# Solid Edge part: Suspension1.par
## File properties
Author: KULL
Template: Iso Metric Part.par
Last saved by: KULL
Revision: 5
Application: Solid Edge
Accuracy: 0,990
Face Style: Model Default
Fill Style: Normal
Coef. of Thermal Exp: 0.0
Thermal Conductivity: 0.0
Specific Heat: 0.0
Modulus of Elasticity: 0.0
Poisson's Ratio: 0.0
Yield Stress: 0.0
Ultimate Stress: 0.0
Elongation: 0.0
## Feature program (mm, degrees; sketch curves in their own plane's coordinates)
sketch for "unnamed RevolvedProtrusion 1" plane through (0, 0, 0) normal (1, 0, 0) x-axis (0, 1, 0)
  line (73.196, 15.5693) -> (77.2742, 17.8066)
  line (73.196, 15.5693) -> (74.5585, 13.0856)
  arc centre (63.4726, 33.2936) radius 23.0491 from (74.5585, 13.0856) to (80.8832, 18.1896) ccw
  line (80.2099, 19.417) -> (80.8832, 18.1896)
  line (79.3784, 18.9609) -> (80.2099, 19.417)
revolve "unnamed RevolvedProtrusion 1" add finite 360 deg
sketch for "ExtrudedProtrusion_1" plane through (1.5, 0, 0) normal (1, 0, 0) x-axis (0, 1, 0)
  arc centre (76.2697, 9.9663) radius 3 from (79.1872, 10.6649) to (74.1129, 7.8811) cw
  line (74.1129, 7.8811) -> (70.4123, 11.7087)
  line (70.4123, 11.7087) -> (77.9476, 15.8425)
  line (79.1872, 10.6649) -> (77.9476, 15.8425)
extrude "ExtrudedProtrusion_1" add finite 2.4 along +normal
mirror "unnamed Mirror 1" of "ExtrudedProtrusion_1" about plane through (0, 0, 0) normal (1, 0, 0)
extrude "unnamed Protrusion 1" add finite 2.4
sketch for "ExtrudedProtrusion_3" plane through (0, 0, 0) normal (1, 0, 0) x-axis (0, 1, 0)
  circle centre (76.2697, 9.9663) radius 1.5
extrude "ExtrudedProtrusion_3" add finite 10 symmetric
fillet "Round_1" radius 0.4
fillet "Round_2" radius 0.8
fillet "Round_3" radius 0.8
fillet "Round_4" radius 0.8
fillet "Round_5" radius 0.2
body pattern "unnamed BodyPattern 1"
pattern "unnamed Pattern 1"
sketch used by "ExtrudedProtrusion_4" plane through (0, 73.196, 15.5693) normal (0, -0.480968, 0.876738) x-axis (0, 0.876738, 0.480968)
extrude "ExtrudedProtrusion_4" add finite 19.3627 along +normal
sketch used by "ExtrudedProtrusion_5" plane through (0, 59.9207, 39.7682) normal (0, 0.480968, -0.876738) x-axis (1, 0, 0)
extrude "ExtrudedProtrusion_5" add finite 18.621 along +normal
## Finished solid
Body 1: solid body, 83 faces, 152 edges, 72 vertices.
  Faces by surface: torus 26, plane 25, cylinder 22, blend 8, sphere 2
  Edges by curve: circle 96, line 32, intersection 24
Bounding box of the edges (mm; curved faces can reach further): 16.000 x 28.107 x 41.405, from (-8, 52.5049, 6.9663) to (8, 80.6118, 48.3711).
Cylindrical faces by radius (mm): R0.8 x8, R1.5 x6, R3 x5, R4 x1, R8 x2
Toroidal faces (ring radius, tube radius in mm): R1.1 r0.4 x4, R2.2 r0.8 x4, R5.8516 r1.2 x2, R7.2 r0.8 x2, R7.8 r0.2 x2, R21.2565 r0.8 x8, R23.3814 r0.8 x4
Spherical faces by radius (mm): R23.0491 x2
Planar faces by outward normal: +x 6, -x 6, oblique 13
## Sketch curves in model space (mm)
circle centre (0, 59.9207, 39.7682) radius 4
circle centre (0, 73.196, 15.5693) radius 3
line (0, 73.196, 15.5693) -> (0, 59.9207, 39.7682)
line (0, 66.5584, 27.6687) -> (0, 78.9436, 34.4631)
line (0, 76.2697, 9.9663) -> (0, 56.847, 45.3711)
line (1.5, 70.4123, 11.7087) -> (1.5, 77.9476, 15.8425)
line (1.5, 74.1129, 7.8811) -> (1.5, 70.4123, 11.7087)
arc centre (1.5, 76.2697, 9.9663) radius 3 from (1.5, 79.1872, 10.6649) through (1.5, 77.634, 7.2945) to (1.5, 74.1129, 7.8811)
line (1.5, 79.1872, 10.6649) -> (1.5, 77.9476, 15.8425)
circle centre (0, 56.847, 45.3711) radius 3
circle centre (0, 76.2697, 9.9663) radius 3
circle centre (0, 56.847, 45.3711) radius 1.5
circle centre (0, 76.2697, 9.9663) radius 1.5
arc centre (0, 78.3263, 18.3837) radius 1.2 from (0, 79.3784, 18.9609) through (0, 78.872, 17.315) to (0, 77.2742, 17.8066)
line (0, 79.3784, 18.9609) -> (0, 80.2099, 19.417)
line (0, 80.2099, 19.417) -> (0, 80.8832, 18.1896)
arc centre (0, 63.4726, 33.2936) radius 23.0491 from (0, 74.5585, 13.0856) through (0, 77.9476, 15.3566) to (0, 80.8832, 18.1896)
line (0, 73.196, 15.5693) -> (0, 74.5585, 13.0856)
line (0, 73.196, 15.5693) -> (0, 77.2742, 17.8066)
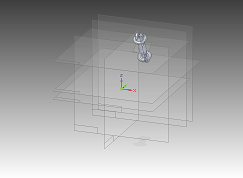
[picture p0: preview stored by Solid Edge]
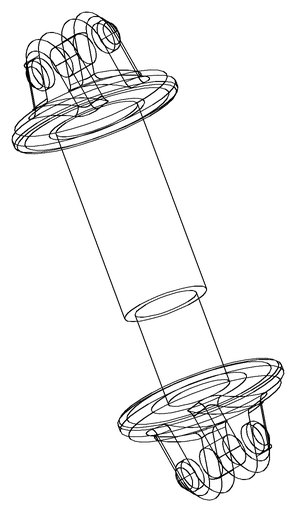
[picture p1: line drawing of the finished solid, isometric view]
